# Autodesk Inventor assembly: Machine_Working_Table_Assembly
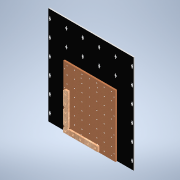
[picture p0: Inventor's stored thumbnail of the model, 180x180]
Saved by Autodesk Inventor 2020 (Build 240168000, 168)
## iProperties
Created: 2020-02
Part Number: Machine_Working_Table_Assembly
Document SubType Name: Assembly
Designer: mmg
Author: mmg
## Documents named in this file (4)
- C:\Users\mmg\OneDrive - BTH\MT1462\Lärare\Fräsmaskinen\WasteTable\Machine_Working_Table_Assembly.iam
- C:\Users\mmg\OneDrive - BTH\MT1462\Lärare\Fräsmaskinen\WasteTable\Machine_Base_Table.ipt
- C:\Users\mmg\OneDrive - BTH\MT1462\Lärare\Fräsmaskinen\WasteTable\Machine_Working_Table.ipt
- C:\Users\mmg\OneDrive - BTH\MT1462\Lärare\Fräsmaskinen\WasteTable\Angular_Support.ipt
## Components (3 placed, 3 different names)
1. Machine_Base_Table:1 — Mate:1, Mate:2, Mate:3
2. Machine_Working_Table:1 — Mate:1, Mate:2, Mate:3, Mate:4, Mate:5, Mate:6
3. Angular_Support:1 — Mate:4, Mate:5, Mate:6
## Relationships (6: Mate 6)
- Mate:1: Machine_Base_Table:1 ↔ Machine_Working_Table:1
- Mate:2: Machine_Base_Table:1 ↔ Machine_Working_Table:1
- Mate:3: Machine_Base_Table:1 ↔ Machine_Working_Table:1
- Mate:4: Machine_Working_Table:1 ↔ Angular_Support:1
- Mate:5: Machine_Working_Table:1 ↔ Angular_Support:1
- Mate:6: Machine_Working_Table:1 ↔ Angular_Support:1
